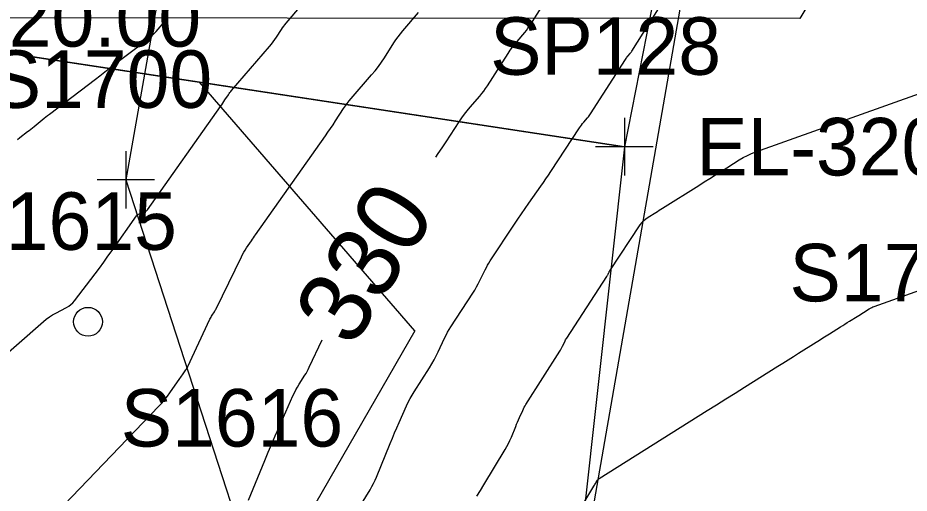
# Model space of a CAD drawing. Extents: x 816928 to 825690, y 436959 to 448212.
# Drawn here: x 819397.1 to 819459, y 445672 to 445705 of the extents above; entities that cross this region are included whole.
import ezdxf

# ---------------------------------------------------------------- set-up
doc = ezdxf.new("R2010")
doc.units = 0
for name, color, linetype in [('SURVEY - CONTOURS - Index with Text', 7, 'Continuous'), ('SURVEY - CONTOURS - Intermediate with optional Text', 7, 'Continuous'), ('SURVEY - DTM - Breaklines', 7, 'Continuous'), ('SURVEY - DTM - Breaklines - Points - Locators', 7, 'Continuous'), ('SURVEY - DTM - Breaklines - Points - Numbers', 7, 'Continuous'), ('SURVEY - DTM - Spot Points - Locators', 7, 'Continuous'), ('SURVEY - DTM - Spot Points - Point Numbers', 7, 'Continuous'), ('SURVEY - PROPERTY - Parcels', 7, 'Continuous'), ('SURVEY - PROPERTY - Property Lines', 7, 'Continuous'), ('SURVEY - PROPERTY - Property Lines - Points - Elevations', 7, 'Continuous'), ('SURVEY - PROPERTY - Property Lines - Points - Locators', 7, 'Continuous'), ('SURVEY - PROPERTY - Property Lines - Points - Numbers', 7, 'Continuous'), ('SURVEY - PROPERTY - Property Lines Text', 7, 'Continuous'), ('SURVEY - PROPERTY - Station and Offset Flags', 7, 'Continuous')]:
    doc.layers.add(name, color=color, linetype=linetype)

msp = doc.modelspace()

# ---------------------------------------------------------------- linework, layer by layer
at = {"layer": 'SURVEY - CONTOURS - Index with Text'}
for points in [[(819426.123, 445695.344), (819426.287, 445695.584), (819426.563, 445695.993), (819426.835, 445696.405), (819427.752, 445697.805), (819427.928, 445698.065), (819428.113, 445698.32), (819428.306, 445698.567), (819428.508, 445698.809), (819429.18, 445699.587), (819429.321, 445699.757), (819429.456, 445699.931), (819429.584, 445700.109), (819429.707, 445700.292), (819431.162, 445702.559), (819431.304, 445702.772), (819431.452, 445702.98), (819431.607, 445703.182), (819431.769, 445703.38), (819432.308, 445704.018), (819432.421, 445704.157), (819432.529, 445704.299), (819432.632, 445704.445), (819432.73, 445704.594), (819434.451, 445707.323)], [(819413.096, 445671.499), (819414.231, 445674.258), (819414.468, 445674.829), (819414.709, 445675.398), (819414.954, 445675.965), (819415.203, 445676.531), (819416.19, 445678.753), (819416.286, 445678.958), (819416.389, 445679.159), (819416.499, 445679.356), (819416.617, 445679.549), (819417.015, 445680.174), (819417.098, 445680.309), (819417.177, 445680.446), (819417.251, 445680.586), (819417.32, 445680.728), (819418.212, 445682.636)]]:
    msp.add_lwpolyline(points, dxfattribs=at)
at = {"layer": 'SURVEY - CONTOURS - Intermediate with optional Text'}
for points in [[(819382.497, 445669.616), (819398.837, 445683.911), (819399.037, 445684.076), (819399.246, 445684.229), (819399.463, 445684.368), (819399.69, 445684.495), (819400.443, 445684.889), (819400.598, 445684.981), (819400.74, 445685.088), (819400.87, 445685.21), (819400.987, 445685.347), (819402.422, 445687.225), (819402.727, 445687.629), (819403.028, 445688.036), (819403.325, 445688.447), (819403.617, 445688.86), (819405.299, 445691.271), (819405.328, 445691.306), (819405.361, 445691.336), (819405.398, 445691.36), (819405.439, 445691.379), (819405.582, 445691.431), (819405.612, 445691.443), (819405.642, 445691.454), (819405.673, 445691.465), (819405.703, 445691.477), (819405.917, 445691.556), (819405.961, 445691.576), (819406, 445691.601), (819406.035, 445691.633), (819406.065, 445691.67), (819411.157, 445698.873), (819411.234, 445698.983), (819411.31, 445699.093), (819411.385, 445699.204), (819411.458, 445699.316), (819411.698, 445699.682), (819411.751, 445699.76), (819411.806, 445699.835), (819411.863, 445699.909), (819411.923, 445699.981), (819414.568, 445703.045), (819414.694, 445703.196), (819414.814, 445703.351), (819414.929, 445703.511), (819415.038, 445703.674), (819415.386, 445704.215), (819415.462, 445704.33), (819415.542, 445704.442), (819415.625, 445704.551), (819415.712, 445704.658), (819417.89, 445707.234)], [(819420.957, 445671.234), (819421.551, 445672.22), (819421.675, 445672.434), (819421.789, 445672.652), (819421.896, 445672.874), (819421.994, 445673.1), (819422.956, 445675.437), (819423.107, 445675.8), (819423.26, 445676.162), (819423.416, 445676.523), (819423.574, 445676.882), (819424.095, 445678.056), (819424.211, 445678.305), (819424.337, 445678.549), (819424.471, 445678.789), (819424.614, 445679.023), (819425.675, 445680.688), (819425.843, 445680.961), (819426.002, 445681.239), (819426.152, 445681.523), (819426.292, 445681.811), (819426.737, 445682.761), (819426.835, 445682.963), (819426.941, 445683.161), (819427.053, 445683.355), (819427.172, 445683.545), (819428.694, 445685.887), (819428.829, 445686.101), (819428.957, 445686.32), (819429.078, 445686.542), (819429.193, 445686.768), (819429.557, 445687.512), (819429.637, 445687.67), (819429.723, 445687.825), (819429.813, 445687.977), (819429.909, 445688.127), (819431.591, 445690.67), (819431.837, 445691.039), (819432.086, 445691.405), (819432.338, 445691.77), (819432.592, 445692.133), (819433.428, 445693.315), (819433.606, 445693.569), (819433.781, 445693.825), (819433.955, 445694.082), (819434.126, 445694.341), (819436.107, 445697.369), (819436.178, 445697.473), (819436.251, 445697.574), (819436.328, 445697.672), (819436.408, 445697.768), (819436.675, 445698.078), (819436.731, 445698.145), (819436.785, 445698.214), (819436.836, 445698.285), (819436.884, 445698.358), (819439.314, 445702.14), (819439.353, 445702.2), (819439.394, 445702.258), (819439.438, 445702.315), (819439.483, 445702.37), (819439.634, 445702.548), (819439.665, 445702.587), (819439.695, 445702.626), (819439.724, 445702.667), (819439.752, 445702.709), (819442.407, 445706.921)], [(819394.757, 445665.433), (819406.864, 445678.02), (819407.069, 445678.243), (819407.266, 445678.473), (819407.454, 445678.711), (819407.632, 445678.956), (819408.33, 445679.956), (819408.387, 445680.037), (819408.444, 445680.119), (819408.501, 445680.2), (819408.557, 445680.281), (819408.743, 445680.547), (819408.781, 445680.604), (819408.817, 445680.664), (819408.85, 445680.724), (819408.881, 445680.786), (819410.415, 445684.068), (819410.452, 445684.143), (819410.491, 445684.217), (819410.533, 445684.289), (819410.578, 445684.36), (819410.727, 445684.59), (819410.758, 445684.64), (819410.788, 445684.69), (819410.816, 445684.742), (819410.842, 445684.794), (819412.607, 445688.404), (819412.69, 445688.566), (819412.777, 445688.725), (819412.87, 445688.881), (819412.968, 445689.035), (819413.296, 445689.53), (819413.367, 445689.636), (819413.438, 445689.742), (819413.51, 445689.847), (819413.584, 445689.951), (819418.441, 445696.823), (819418.621, 445697.08), (819418.799, 445697.339), (819418.974, 445697.599), (819419.147, 445697.86), (819419.708, 445698.718), (819419.831, 445698.9), (819419.96, 445699.077), (819420.095, 445699.25), (819420.236, 445699.418), (819421.661, 445701.069), (819421.899, 445701.354), (819422.126, 445701.648), (819422.343, 445701.949), (819422.549, 445702.258), (819423.205, 445703.28), (819423.349, 445703.497), (819423.5, 445703.708), (819423.658, 445703.915), (819423.823, 445704.116), (819424.913, 445705.406)], [(819397.041, 445696.578), (819397.2, 445696.708), (819397.735, 445697.117), (819397.849, 445697.205), (819397.963, 445697.295), (819398.075, 445697.385), (819398.187, 445697.476), (819398.753, 445697.942), (819398.875, 445698.041), (819398.998, 445698.139), (819399.122, 445698.235), (819399.246, 445698.331), (819402.452, 445700.755), (819402.558, 445700.836), (819402.664, 445700.918), (819402.769, 445701.002), (819402.874, 445701.086), (819403.214, 445701.363), (819403.287, 445701.421), (819403.361, 445701.48), (819403.435, 445701.537), (819403.51, 445701.593), (819405.874, 445703.348), (819406.089, 445703.517), (819406.293, 445703.696), (819406.487, 445703.887), (819406.67, 445704.088), (819407.476, 445705.021), (819407.489, 445705.038)], [(819428.983, 445671.76), (819429.223, 445672.158), (819429.462, 445672.556), (819430.936, 445675.002), (819431.058, 445675.213), (819431.172, 445675.429), (819431.277, 445675.648), (819431.375, 445675.872), (819431.68, 445676.615), (819431.745, 445676.771), (819431.811, 445676.925), (819431.877, 445677.08), (819431.945, 445677.234), (819432.168, 445677.736), (819432.218, 445677.842), (819432.271, 445677.947), (819432.329, 445678.049), (819432.39, 445678.149), (819434.744, 445681.843), (819434.798, 445681.931), (819434.849, 445682.021), (819434.897, 445682.112), (819434.943, 445682.205), (819435.086, 445682.511), (819435.118, 445682.576), (819435.152, 445682.64), (819435.188, 445682.703), (819435.226, 445682.764), (819438.013, 445687.052), (819438.036, 445687.088), (819438.058, 445687.125), (819438.079, 445687.163), (819438.098, 445687.201), (819438.159, 445687.327), (819438.173, 445687.353), (819438.188, 445687.38), (819438.203, 445687.405), (819438.219, 445687.431), (819440.336, 445690.63), (819440.45, 445690.785), (819440.579, 445690.925), (819440.722, 445691.051), (819440.88, 445691.162), (819441.418, 445691.5), (819441.534, 445691.572), (819441.649, 445691.645), (819441.764, 445691.717), (819441.88, 445691.79), (819444.403, 445693.375), (819444.792, 445693.619), (819445.181, 445693.864), (819445.57, 445694.108), (819445.959, 445694.352), (819447.229, 445695.151), (819447.505, 445695.314), (819447.789, 445695.461), (819448.08, 445695.593), (819448.379, 445695.708), (819462.098, 445700.592)], [(819434.438, 445668.021), (819437.122, 445672.473), (819437.155, 445672.529), (819437.188, 445672.584), (819437.221, 445672.639), (819437.255, 445672.694), (819437.363, 445672.874), (819437.388, 445672.911), (819437.417, 445672.944), (819437.45, 445672.974), (819437.486, 445673), (819444.995, 445677.717), (819445.644, 445678.125), (819446.294, 445678.533), (819446.943, 445678.941), (819447.593, 445679.349), (819449.899, 445680.799), (819450.262, 445681.026), (819450.624, 445681.254), (819450.986, 445681.481), (819451.348, 445681.709), (819452.576, 445682.48), (819452.807, 445682.625), (819453.038, 445682.771), (819453.269, 445682.916), (819453.5, 445683.061), (819454.258, 445683.537), (819454.418, 445683.637), (819454.578, 445683.738), (819454.738, 445683.839), (819454.898, 445683.939), (819455.422, 445684.268), (819455.534, 445684.338), (819455.646, 445684.409), (819455.758, 445684.479), (819455.87, 445684.55), (819456.262, 445684.796), (819456.347, 445684.846), (819456.434, 445684.891), (819456.524, 445684.932), (819456.616, 445684.968), (819460.76, 445686.443)]]:
    msp.add_lwpolyline(points, dxfattribs=at)
at = {"layer": 'SURVEY - DTM - Breaklines'}
for points in [[(819412.601, 445739.334), (819404.566, 445693.768), (819418.819, 445649.871), (819419.764, 445603.429)], [(819429.03, 445605.798), (819435.64, 445662.807), (819444.275, 445712.307), (819447.275, 445731.706)]]:
    msp.add_lwpolyline(points, dxfattribs=at)
at = {"layer": 'SURVEY - DTM - Breaklines - Points - Locators'}
for p, q in [((819404.566, 445695.768), (819404.566, 445691.768)), ((819406.566, 445693.768), (819402.566, 445693.768))]:
    msp.add_line(p, q, dxfattribs=at)
at = {"layer": 'SURVEY - DTM - Spot Points - Locators'}
msp.add_circle((819401.935, 445683.896), 1, dxfattribs=at)
at = {"layer": 'SURVEY - PROPERTY - Parcels'}
for p, q in [((819489.855, 445952.342), (819439.235, 445696.068)), ((819380.12, 445705.028), (819439.235, 445696.068)), ((819439.235, 445696.068), (819380.12, 445705.028)), ((819439.235, 445696.068), (819426.043, 445576.354))]:
    msp.add_line(p, q, dxfattribs=at)
at = {"layer": 'SURVEY - PROPERTY - Property Lines'}
for p, q in [((819489.855, 445952.342), (819439.235, 445696.068)), ((819380.12, 445705.028), (819439.235, 445696.068)), ((819439.235, 445696.068), (819426.043, 445576.354))]:
    msp.add_line(p, q, dxfattribs=at)
at = {"layer": 'SURVEY - PROPERTY - Property Lines - Points - Locators'}
for p, q in [((819439.235, 445698.068), (819439.235, 445694.068)), ((819441.235, 445696.068), (819437.235, 445696.068))]:
    msp.add_line(p, q, dxfattribs=at)
at = {"layer": 'SURVEY - PROPERTY - Property Lines Text'}
msp.add_line((819424.675, 445683.265), (819388.397, 445620.458), dxfattribs=at)
msp.add_lwpolyline([(819424.675, 445683.265), (819409.678, 445700.548)], dxfattribs=at)
at = {"layer": 'SURVEY - PROPERTY - Station and Offset Flags'}
msp.add_line((819470.776, 445737.568), (819451.438, 445704.972), dxfattribs=at)
msp.add_lwpolyline([(819451.438, 445704.972), (819380.12, 445705.028)], dxfattribs=at)

# ---------------------------------------------------------------- texts
at = {"layer": 'SURVEY - CONTOURS - Index with Text'}
msp.add_text('330', height=5, rotation=58.09783, dxfattribs=at).set_placement((819420.292, 445681.97))
at = {"layer": 'SURVEY - DTM - Breaklines - Points - Numbers'}
msp.add_text('S1700', height=4, dxfattribs=at).set_placement((819395.105, 445698.768))
at = {"layer": 'SURVEY - DTM - Spot Points - Point Numbers'}
for s, p in [('S1615', (819392.648, 445688.896)), ('S1710', (819450.718, 445685.313)), ('S1616', (819404.214, 445675.218))]:
    msp.add_text(s, height=4, dxfattribs=at).set_placement(p)
at = {"layer": 'SURVEY - PROPERTY - Property Lines - Points - Elevations'}
for p in [(819385.12, 445703.028), (819444.235, 445694.068)]:
    msp.add_text('EL-320.00', height=4, dxfattribs=at).set_placement(p)
at = {"layer": 'SURVEY - PROPERTY - Property Lines - Points - Numbers'}
msp.add_text('SP128', height=4, dxfattribs=at).set_placement((819429.9, 445701.068))

doc.saveas('drawing.dxf')
